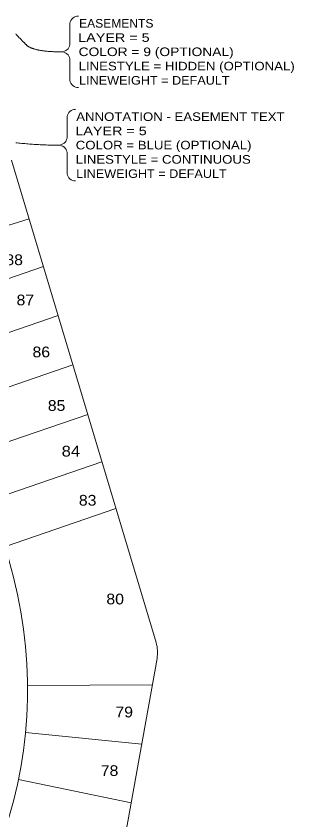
# Model space of a CAD drawing. Extents: x 6387474 to 6390971, y 1972046 to 1973920.
# Drawn here: x 6389745 to 6390004, y 1972779 to 1973528 of the extents above; entities that cross this region are included whole.
import ezdxf

# ---------------------------------------------------------------- set-up
doc = ezdxf.new("R2010")
doc.units = 0
doc.header["$LTSCALE"] = 4
for name, color, linetype, lineweight in [('1', 7, 'Continuous', 13), ('3', 7, 'Continuous', 13), ('4', 7, 'Continuous', 13), ('8', 7, 'Continuous', 13)]:
    doc.layers.add(name, color=color, linetype=linetype, lineweight=lineweight)
doc.layers.add('7', color=7, linetype='Continuous')

msp = doc.modelspace()

# ---------------------------------------------------------------- linework, layer by layer
at = {"layer": '1'}
for p, q in [((6389875.293, 1972944.722), (6389740.695, 1973394.066)), ((6389759.246, 1972274.953), (6389876.154, 1972929.685))]:
    msp.add_line(p, q, dxfattribs=at)
msp.add_arc((6389844.16, 1972935.398), 32.5, 349.87611, 16.67291, dxfattribs=at)
at = {"layer": '3'}
for p, q in [((6389642.202, 1973303.229), (6389757.063, 1973339.423)), ((6389770.394, 1973294.917), (6389657.843, 1973256.331)), ((6389784.098, 1973249.169), (6389673.319, 1973211.19)), ((6389797.825, 1973203.344), (6389688.821, 1973165.973)), ((6389811.683, 1973157.078), (6389704.472, 1973120.322)), ((6389824.899, 1973112.959), (6389719.397, 1973076.789)), ((6389837.948, 1973069.396), (6389734.116, 1973033.799)), ((6389871.789, 1972905.239), (6389755.55, 1972904.52)), ((6389861.919, 1972849.963), (6389753.591, 1972860.659)), ((6389852.147, 1972795.238), (6389747.006, 1972816.957))]:
    msp.add_line(p, q, dxfattribs=at)
at = {"layer": '4'}
msp.add_arc((6389335.562, 1972901.304), 420, 307.91924, 18.92365, dxfattribs=at)
at = {"layer": '8'}
for p, q in [((6389795.013, 1973521.478), (6389795.013, 1973501.498)), ((6389795.013, 1973468.192), (6389795.013, 1973488.172)), ((6389792.336, 1973434.547), (6389792.336, 1973414.567)), ((6389792.336, 1973381.261), (6389792.336, 1973401.241))]:
    msp.add_line(p, q, dxfattribs=at)
for points in [[(6389755.553, 1973500.334), (6389755.257, 1973500.564), (6389754.974, 1973500.794), (6389754.706, 1973501.034), (6389754.451, 1973501.274), (6389754.202, 1973501.514), (6389753.947, 1973501.764), (6389753.688, 1973502.024), (6389753.424, 1973502.284), (6389753.155, 1973502.554), (6389752.882, 1973502.824), (6389752.604, 1973503.104), (6389752.321, 1973503.394), (6389752.034, 1973503.684), (6389751.742, 1973503.974), (6389751.446, 1973504.274), (6389751.144, 1973504.584), (6389750.838, 1973504.894), (6389750.528, 1973505.214), (6389750.212, 1973505.534), (6389749.892, 1973505.864), (6389749.568, 1973506.194), (6389749.238, 1973506.534), (6389748.904, 1973506.884), (6389748.566, 1973507.234), (6389748.222, 1973507.584), (6389747.874, 1973507.944), (6389747.522, 1973508.314), (6389747.164, 1973508.684), (6389746.802, 1973509.064), (6389746.436, 1973509.454), (6389746.064, 1973509.834), (6389745.688, 1973510.234), (6389745.308, 1973510.634), (6389744.922, 1973511.034), (6389744.532, 1973511.454)], [(6389787.127, 1973494.834), (6389786.149, 1973494.834), (6389785.184, 1973494.844), (6389784.234, 1973494.854), (6389783.297, 1973494.874), (6389782.374, 1973494.894), (6389781.465, 1973494.914), (6389780.57, 1973494.944), (6389779.689, 1973494.984), (6389778.822, 1973495.024), (6389777.969, 1973495.064), (6389777.129, 1973495.114), (6389776.304, 1973495.164), (6389775.493, 1973495.224), (6389774.695, 1973495.284), (6389773.911, 1973495.354), (6389773.142, 1973495.424), (6389772.386, 1973495.494), (6389771.644, 1973495.574), (6389770.916, 1973495.664), (6389770.202, 1973495.754), (6389769.502, 1973495.844), (6389768.816, 1973495.944), (6389768.144, 1973496.044), (6389767.486, 1973496.154), (6389766.841, 1973496.264), (6389766.211, 1973496.384), (6389765.594, 1973496.504), (6389764.992, 1973496.634), (6389764.403, 1973496.764), (6389763.828, 1973496.894), (6389763.267, 1973497.034), (6389762.72, 1973497.184), (6389762.187, 1973497.334), (6389761.668, 1973497.484), (6389761.163, 1973497.644), (6389760.672, 1973497.804), (6389760.195, 1973497.974), (6389759.731, 1973498.144), (6389759.282, 1973498.324), (6389758.846, 1973498.504), (6389758.425, 1973498.684), (6389758.017, 1973498.874), (6389757.623, 1973499.074), (6389757.243, 1973499.274), (6389756.878, 1973499.474), (6389756.526, 1973499.684), (6389756.187, 1973499.894), (6389755.863, 1973500.114), (6389755.553, 1973500.334)], [(6389784.45, 1973407.904), (6389783.023, 1973407.904), (6389781.595, 1973407.914), (6389780.167, 1973407.934), (6389778.74, 1973407.954), (6389777.313, 1973407.974), (6389775.886, 1973408.004), (6389774.46, 1973408.044), (6389773.033, 1973408.084), (6389771.607, 1973408.134), (6389770.181, 1973408.194), (6389768.755, 1973408.254), (6389767.33, 1973408.314), (6389765.905, 1973408.394), (6389764.48, 1973408.464), (6389763.055, 1973408.554), (6389761.63, 1973408.634), (6389760.206, 1973408.734), (6389758.782, 1973408.834), (6389757.358, 1973408.944), (6389755.934, 1973409.054), (6389754.511, 1973409.174), (6389753.088, 1973409.294), (6389751.665, 1973409.424), (6389750.242, 1973409.554), (6389748.819, 1973409.694), (6389747.397, 1973409.844), (6389745.975, 1973409.994), (6389744.553, 1973410.154)]]:
    msp.add_lwpolyline(points, dxfattribs=at)
for centre, start, end in [((6389802.903, 1973520.141), 90, 170.38048), ((6389787.127, 1973502.835), 270, 350.38048), ((6389787.127, 1973486.835), 9.61952, 90), ((6389802.902, 1973469.529), 189.61952, 270), ((6389800.226, 1973433.21), 90, 170.38048), ((6389784.45, 1973415.904), 270, 350.38048), ((6389784.45, 1973399.904), 9.61952, 90), ((6389800.225, 1973382.598), 189.61952, 270)]:
    msp.add_arc(centre, 8, start, end, dxfattribs=at)

# ---------------------------------------------------------------- texts
at = {"layer": '7'}
for s, width, p in [('88', 1.1, (6389734.908, 1973296.146)), ('87', 1.1, (6389745.301, 1973258.677)), ('86', 1.1, (6389760.169, 1973210.258)), ('85', 1.1, (6389774.422, 1973160.374)), ('84', 1.15, (6389787.326, 1973117.858)), ('83', 1.1, (6389803.364, 1973072.118)), ('80', 1.1, (6389828.985, 1972980.134)), ('79', 1.1, (6389837.412, 1972874.874)), ('78', 1.1, (6389823.77, 1972820.269))]:
    msp.add_text(s, height=10, dxfattribs=dict(at, width=width)).set_placement(p)
at = {"layer": '8'}
for s, width, p in [('EASEMENTS', 1.05, (6389803.547, 1973517.375)), ('LAYER = 5', 1.25, (6389802.735, 1973504.127)), ('COLOR = 9 (OPTIONAL)', 1.2, (6389803.127, 1973490.869)), ('LINESTYLE = HIDDEN (OPTIONAL)', 1.15, (6389803.127, 1973477.549)), ('LINEWEIGHT = DEFAULT', 1.1, (6389803.519, 1973464.291)), ('ANNOTATION - EASEMENT TEXT', 1.15, (6389800.87, 1973430.444)), ('LAYER = 5', 1.25, (6389800.058, 1973417.196)), ('COLOR = BLUE (OPTIONAL)', 1.15, (6389800.45, 1973403.938)), ('LINESTYLE = CONTINUOUS', 1.15, (6389800.45, 1973390.618)), ('LINEWEIGHT = DEFAULT', 1.1, (6389800.842, 1973377.36))]:
    msp.add_text(s, height=8, dxfattribs=dict(at, width=width)).set_placement(p)

doc.saveas('drawing.dxf')
